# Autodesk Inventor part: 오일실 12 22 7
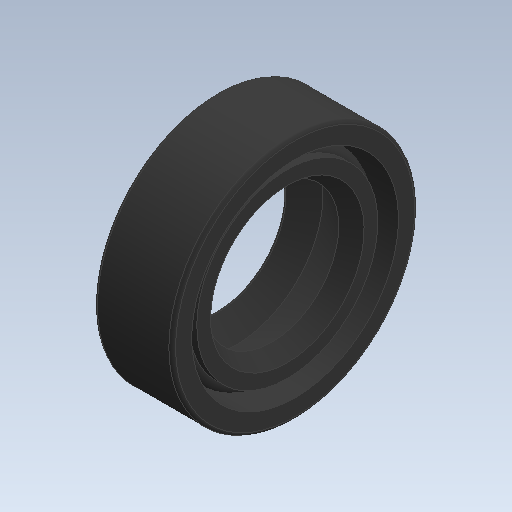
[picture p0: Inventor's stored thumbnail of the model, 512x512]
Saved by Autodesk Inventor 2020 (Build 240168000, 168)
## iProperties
Created: 2024-07
Part Number: 오일실 12 22 7
Material: 고무
Description: 오일-실
Document SubType Name: Modeling
Designer: oem
Density: 0.93 g/cm^3
Appearance: 기본값
Mass: 1.25383 g
Surface Area: 18.4996 cm^2
Volume: 1.3482 cm^3
Sending System: Autodesk Inventor 2025
Preprocessor: ST-DEVELOPER v20
Author: jhkim
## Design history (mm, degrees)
feature "Solid1"
node "솔리드1"
